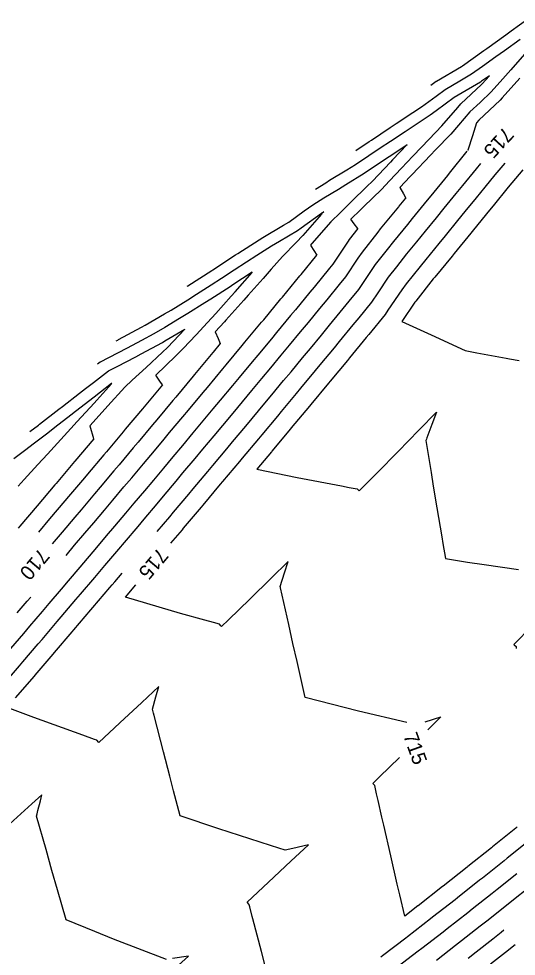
# Model space of a CAD drawing. Extents: x 1487507 to 1489130, y 497211 to 499439.
# Drawn here: x 1488402.4 to 1488484.6, y 498736.1 to 498891 of the extents above; entities that cross this region are included whole.
import ezdxf

# ---------------------------------------------------------------- set-up
doc = ezdxf.new("R2010")
doc.units = 0
for name, color, linetype in [('Prop CMT Ditch DDE', 7, 'Continuous'), ('Prop Drainage Ditch Flow Line', 7, 'Continuous'), ('Prop Drainage Structure Pipe Outlet Channel Detail CELL', 7, 'Continuous')]:
    doc.layers.add(name, color=color, linetype=linetype)

msp = doc.modelspace()

# ---------------------------------------------------------------- linework, layer by layer
at = {"layer": 'Prop CMT Ditch DDE'}
for points in [[(1488470.48, 498879.98), (1488471.36, 498880.63), (1488471.38, 498880.64), (1488475.53, 498883.09), (1488475.71, 498883.2), (1488479.21, 498885.69), (1488479.73, 498886.06), (1488482.84, 498888.3), (1488483.73, 498888.95), (1488486.49, 498890.96)], [(1488458.06, 498869.2), (1488460.25, 498870.67), (1488460.63, 498870.92), (1488463.74, 498872.99), (1488464.75, 498873.66), (1488467.51, 498875.47), (1488468.9, 498876.38), (1488471.35, 498878.18), (1488472.85, 498879.29), (1488475.26, 498880.7), (1488477.19, 498881.85), (1488479.02, 498883.15), (1488481.21, 498884.72), (1488482.62, 498885.73), (1488485.22, 498887.61)], [(1488485.96, 498885.11), (1488483.67, 498882.5), (1488482.35, 498881.02), (1488480.45, 498878.88), (1488478.6, 498877.14), (1488476.91, 498875.56), (1488475.05, 498873.4), (1488473.75, 498871.9), (1488471.23, 498869.28), (1488470.39, 498868.41), (1488467.35, 498865.2), (1488467.06, 498864.91), (1488465.32, 498863.06), (1488465.92, 498862.03), (1488466.33, 498861.33)], [(1488458.41, 498856.3), (1488457.81, 498857.08), (1488457.24, 498857.84), (1488458.83, 498859.38), (1488459.39, 498859.94), (1488462.29, 498862.76), (1488463.65, 498864.2), (1488465.6, 498866.27), (1488467.46, 498868.23), (1488468.93, 498869.77), (1488471.29, 498872.22), (1488472.28, 498873.25), (1488474.93, 498876.32), (1488475.44, 498876.91), (1488478.81, 498880.07), (1488478.97, 498880.23), (1488480.14, 498881.54), (1488480.13, 498881.55), (1488478.84, 498880.62), (1488478.67, 498880.5), (1488474.98, 498878.32), (1488474.32, 498877.93), (1488471.33, 498875.73), (1488470.37, 498875.02), (1488467.54, 498873.17), (1488466.21, 498872.3), (1488463.79, 498870.69), (1488462.09, 498869.56), (1488460.2, 498868.29), (1488457.99, 498866.81), (1488456.59, 498865.95), (1488453.74, 498864.21), (1488453.11, 498863.82), (1488451.39, 498862.76)], [(1488485.15, 498881.16), (1488482.24, 498877.88), (1488481.93, 498877.53), (1488478.39, 498874.22), (1488478.39, 498874.21), (1488478.01, 498873.78), (1488477.34, 498871.64), (1488476.6, 498869.27), (1488476.63, 498869.23)], [(1488430.18, 498846.77), (1488430.28, 498846.83), (1488430.29, 498846.84), (1488434.25, 498849.39), (1488434.42, 498849.5), (1488438.2, 498851.93), (1488438.55, 498852.16), (1488442.11, 498854.45), (1488442.69, 498854.83), (1488446.12, 498856.86), (1488446.98, 498857.37), (1488449.54, 498859.21), (1488450.95, 498860.23), (1488452.78, 498861.35), (1488455.19, 498862.83), (1488456.41, 498863.58), (1488459.44, 498865.44), (1488460.16, 498865.92), (1488463.55, 498868.19), (1488463.83, 498868.38), (1488466.55, 498870.19), (1488466.56, 498870.18), (1488464.14, 498867.64), (1488463.81, 498867.29), (1488460.83, 498864.13), (1488459.9, 498863.22), (1488457.37, 498860.76), (1488455.53, 498858.96), (1488453.92, 498857.39), (1488450.81, 498853.84), (1488450.74, 498853.76), (1488450.55, 498853.56), (1488450.61, 498853.45), (1488451.6, 498851.89)], [(1488425.24, 498806.23), (1488427.31, 498808.68), (1488427.95, 498809.44), (1488430.46, 498812.42), (1488431.17, 498813.27), (1488433.61, 498816.17), (1488434.44, 498817.16), (1488436.75, 498819.92), (1488437.71, 498821.06), (1488439.89, 498823.67), (1488440.94, 498824.94), (1488443.02, 498827.43), (1488444.16, 498828.81), (1488446.14, 498831.18), (1488447.36, 498832.65), (1488449.26, 498834.94), (1488450.56, 498836.5), (1488452.37, 498838.7), (1488453.74, 498840.36), (1488455.48, 498842.46), (1488456.98, 498844.29), (1488458.57, 498846.23), (1488460.1, 498848.52), (1488461.32, 498850.33), (1488463.29, 498852.84), (1488464.33, 498854.16), (1488466.64, 498856.98), (1488467.42, 498857.93), (1488469.93, 498861), (1488470.49, 498861.7), (1488473.25, 498865.08), (1488473.57, 498865.47), (1488476.49, 498869.07)], [(1488482.67, 498867.09), (1488481.04, 498865.17), (1488479.37, 498863.12), (1488477.96, 498861.38), (1488476.1, 498859.1), (1488474.88, 498857.6), (1488472.85, 498855.12), (1488471.78, 498853.81), (1488469.62, 498851.18), (1488468.69, 498850.03), (1488466.4, 498847.14), (1488465.66, 498846.18), (1488463.38, 498842.8), (1488462.89, 498842.07), (1488460.22, 498838.81), (1488459.79, 498838.28), (1488457.02, 498834.93), (1488456.67, 498834.51), (1488453.82, 498831.07), (1488453.55, 498830.74), (1488450.62, 498827.21), (1488450.41, 498826.96), (1488447.4, 498823.35), (1488447.27, 498823.2), (1488444.19, 498819.5), (1488444.13, 498819.43), (1488441.73, 498816.56), (1488448.37, 498815.18), (1488455.7, 498813.78), (1488456.98, 498813.54), (1488458.28, 498813.32), (1488458.34, 498813.26), (1488458.64, 498812.97), (1488461.58, 498815.93), (1488465.05, 498819.45), (1488468.5, 498822.98), (1488471.38, 498825.95), (1488470.62, 498823.92), (1488469.8, 498821.72), (1488469.72, 498821.5), (1488469.65, 498821.3), (1488470.51, 498815.99), (1488470.86, 498813.75), (1488471.48, 498810.16), (1488472.27, 498805.38), (1488472.47, 498804.28), (1488472.9, 498801.79), (1488476.51, 498801.19), (1488479.27, 498800.79), (1488484.93, 498799.94)], [(1488485.69, 498866.02), (1488483.25, 498863.13), (1488480.74, 498860.06), (1488480.16, 498859.34), (1488477.52, 498856.11), (1488477.07, 498855.55), (1488474.32, 498852.18), (1488473.97, 498851.76), (1488471.12, 498848.28), (1488470.86, 498847.97), (1488467.96, 498844.28), (1488467.83, 498844.11), (1488465.69, 498840.94), (1488470.49, 498838.73), (1488476.16, 498836.15), (1488478.09, 498835.78), (1488482.92, 498834.89), (1488483.44, 498834.79), (1488485.08, 498834.49)], [(1488399.82, 498780.97), (1488402.47, 498784.05), (1488403.02, 498784.69), (1488405.59, 498787.7), (1488406.21, 498788.42), (1488408.71, 498791.35), (1488409.39, 498792.15), (1488411.82, 498795.01), (1488412.57, 498795.89), (1488414.93, 498798.67), (1488415.74, 498799.62), (1488416.58, 498800.62), (1488418.91, 498803.35), (1488419.83, 498804.44), (1488422.07, 498807.09), (1488423.06, 498808.27), (1488425.22, 498810.83), (1488426.28, 498812.09), (1488428.36, 498814.57), (1488429.5, 498815.92), (1488431.51, 498818.31), (1488432.79, 498819.85), (1488434.64, 498822.05), (1488436.08, 498823.77), (1488437.77, 498825.8), (1488439.32, 498827.66), (1488440.89, 498829.54), (1488442.54, 498831.53), (1488444.01, 498833.29), (1488445.74, 498835.38), (1488447.12, 498837.04), (1488448.93, 498839.22), (1488450.23, 498840.79), (1488452.11, 498843.07), (1488453.33, 498844.54), (1488455.36, 498847.03), (1488456.4, 498848.31), (1488458.46, 498851.38), (1488459.15, 498852.4), (1488461.74, 498855.7), (1488462.16, 498856.23), (1488465.15, 498859.88), (1488465.23, 498859.98), (1488466.33, 498861.33)], [(1488458.41, 498856.3), (1488456.98, 498854.47), (1488456.82, 498854.23), (1488454.24, 498850.39), (1488453.73, 498849.77), (1488451.17, 498846.63), (1488450.47, 498845.79), (1488448.08, 498842.88), (1488447.29, 498841.94), (1488444.98, 498839.14), (1488444.11, 498838.1), (1488441.87, 498835.4), (1488440.92, 498834.26), (1488438.76, 498831.66), (1488437.7, 498830.39), (1488435.65, 498827.92), (1488434.45, 498826.49), (1488432.53, 498824.18), (1488431.14, 498822.53), (1488429.4, 498820.45), (1488427.83, 498818.57), (1488426.27, 498816.71), (1488424.61, 498814.75), (1488423.13, 498812.98), (1488421.4, 498810.93), (1488419.98, 498809.25), (1488418.17, 498807.11), (1488416.83, 498805.52), (1488414.94, 498803.29), (1488413.67, 498801.79), (1488412.46, 498800.36), (1488410.51, 498798.07), (1488409.35, 498796.7), (1488407.34, 498794.34), (1488406.23, 498793.05), (1488404.16, 498790.62), (1488403.12, 498789.39), (1488400.98, 498786.89)], [(1488410.17, 498802.28), (1488411.6, 498803.96), (1488413.29, 498805.96), (1488414.75, 498807.69), (1488416.52, 498809.78), (1488417.9, 498811.41), (1488419.74, 498813.6), (1488421.04, 498815.13), (1488422.95, 498817.41), (1488424.17, 498818.86), (1488426.15, 498821.23), (1488427.29, 498822.58), (1488429.49, 498825.21), (1488430.41, 498826.31), (1488432.82, 498829.2), (1488433.53, 498830.04), (1488436.08, 498833.11), (1488436.64, 498833.77), (1488439.3, 498836.98), (1488439.74, 498837.51), (1488442.49, 498840.82), (1488442.84, 498841.24), (1488445.66, 498844.66), (1488445.93, 498844.98), (1488448.84, 498848.5), (1488449.01, 498848.72), (1488451.6, 498851.89)], [(1488426.11, 498830.48), (1488425.67, 498831.09), (1488425, 498832.07), (1488428.33, 498835.25), (1488429.51, 498836.47), (1488431.66, 498838.72), (1488433.56, 498840.78), (1488434.93, 498842.26), (1488437.46, 498845.11), (1488438.12, 498845.86), (1488440.96, 498849.06), (1488440.95, 498849.06), (1488440.95, 498849.07), (1488437.76, 498847.01), (1488437.28, 498846.69), (1488434.08, 498844.63), (1488433.14, 498844.02), (1488430.3, 498842.26), (1488428.94, 498841.42), (1488426.48, 498839.96), (1488424.68, 498838.9), (1488422.63, 498837.79), (1488420.28, 498836.53), (1488418.68, 498835.7), (1488415.81, 498834.23), (1488415.36, 498833.88)], [(1488404.22, 498822.76), (1488405.61, 498823.82), (1488405.78, 498823.95), (1488408.98, 498826.43), (1488409.59, 498826.9), (1488412.4, 498829.08), (1488413.4, 498829.85), (1488414.7, 498830.86), (1488417.22, 498832.81), (1488418.61, 498833.52), (1488421.69, 498835.11), (1488422.59, 498835.59), (1488426.1, 498837.48), (1488426.5, 498837.72), (1488429.8, 498839.68), (1488429.81, 498839.67), (1488426.92, 498836.66), (1488426.12, 498835.9), (1488423.44, 498833.34), (1488421.13, 498831.23), (1488419.89, 498830.1), (1488417.09, 498827.01), (1488416.66, 498826.53), (1488414.1, 498823.72), (1488414.74, 498821.61), (1488414.75, 498821.58)], [(1488402.27, 498813.76), (1488403.26, 498814.84), (1488405.53, 498817.3), (1488407.13, 498819.04), (1488408.79, 498820.84), (1488410.98, 498823.25), (1488412.03, 498824.4), (1488414.8, 498827.45), (1488415.26, 498827.96), (1488417.72, 498830.67), (1488417.72, 498830.68), (1488417.71, 498830.68), (1488414.8, 498828.43), (1488411.75, 498826.06), (1488410.99, 498825.47), (1488408.35, 498823.42), (1488407.17, 498822.51), (1488404.95, 498820.82), (1488403.33, 498819.59), (1488401.55, 498818.23)], [(1488426.11, 498830.48), (1488423.08, 498826.86), (1488422.81, 498826.53), (1488419.97, 498823.15), (1488419.62, 498822.73), (1488416.85, 498819.43), (1488416.42, 498818.92), (1488413.73, 498815.72), (1488413.22, 498815.12), (1488410.6, 498812.02), (1488410, 498811.31), (1488407.46, 498808.31), (1488405.62, 498806.14)], [(1488414.76, 498821.58), (1488411.64, 498817.88), (1488411.56, 498817.79), (1488408.52, 498814.18), (1488408.35, 498813.98), (1488405.39, 498810.48), (1488402.56, 498807.14), (1488402.26, 498806.78)], [(1488401.85, 498778.76), (1488404.94, 498782.36), (1488405.06, 498782.49), (1488408.06, 498786), (1488408.26, 498786.23), (1488411.18, 498789.65), (1488411.45, 498789.97), (1488414.29, 498793.31), (1488414.63, 498793.71), (1488417.41, 498796.97), (1488417.81, 498797.45), (1488418.23, 498797.94), (1488419.43, 498799.36)], [(1488402.11, 498792.81), (1488403.76, 498794.74), (1488404.34, 498795.42)], [(1488487.2, 498790.63), (1488484.18, 498787.59), (1488484.24, 498787.54), (1488484.54, 498787.24), (1488484.59, 498786.93)], [(1488443.23, 498733.82), (1488442.46, 498736.87), (1488441.05, 498742.25), (1488440.95, 498742.62), (1488440.53, 498744.23), (1488440.45, 498744.55), (1488440.43, 498744.63), (1488440.1, 498744.98), (1488440.09, 498744.99), (1488443.65, 498748.31), (1488447.34, 498751.76), (1488450.22, 498754.47), (1488447.63, 498753.88), (1488446.37, 498753.6), (1488445.32, 498753.92), (1488443.94, 498754.37), (1488435.42, 498757.13), (1488429.03, 498759.29), (1488427.96, 498763.42), (1488427.32, 498765.8), (1488426.29, 498769.84), (1488424.72, 498775.84), (1488424.62, 498776.23), (1488424.45, 498776.91), (1488425.01, 498778.9), (1488425.5, 498780.64), (1488422.69, 498778), (1488419.09, 498774.62), (1488415.61, 498771.39), (1488415.28, 498771.74), (1488415.27, 498771.76), (1488414.88, 498771.89), (1488412.97, 498772.58), (1488404.84, 498775.52), (1488400.47, 498777.15)], [(1488426.8, 498735.52), (1488418.04, 498738.91), (1488414.95, 498740.14), (1488410.18, 498742.08), (1488408.78, 498747.03), (1488407.85, 498750.21), (1488406.88, 498753.7), (1488405.3, 498759.22), (1488405.39, 498759.57), (1488405.53, 498760.17), (1488405.93, 498761.75), (1488406.17, 498762.71), (1488404.55, 498761.24), (1488400.89, 498757.93)], [(1488486.59, 498755.08), (1488483.1, 498752.27), (1488482.57, 498751.83), (1488479, 498748.99), (1488478.53, 498748.61), (1488474.89, 498745.73), (1488474.48, 498745.4), (1488470.76, 498742.5), (1488470.41, 498742.23), (1488466.62, 498739.3), (1488466.32, 498739.07), (1488462.46, 498736.12), (1488462.22, 498735.93)], [(1488484.66, 498749.68), (1488481.42, 498747.09), (1488480.62, 498746.45), (1488477.29, 498743.82), (1488476.56, 498743.24), (1488473.16, 498740.58), (1488472.48, 498740.05), (1488469, 498737.37), (1488468.39, 498736.89), (1488464.83, 498734.18)], [(1488471.39, 498735.44), (1488474.55, 498737.88), (1488475.55, 498738.66), (1488478.63, 498741.07), (1488479.69, 498741.91), (1488482.7, 498744.29), (1488483.83, 498745.2), (1488486.75, 498747.53)], [(1488482.55, 498740.37), (1488482.09, 498740.01), (1488480.71, 498738.91), (1488477.94, 498736.75), (1488476.62, 498735.71)], [(1488428.76, 498734.59), (1488430.41, 498736.1), (1488427.78, 498735.67)]]:
    msp.add_lwpolyline(points, dxfattribs=at)
at = {"layer": 'Prop Drainage Ditch Flow Line'}
for points in [[(1488427.52, 498804.3), (1488429.4, 498806.53), (1488429.61, 498806.78), (1488432.56, 498810.28), (1488432.84, 498810.61), (1488435.72, 498814.04), (1488436.09, 498814.48), (1488438.87, 498817.79), (1488439.33, 498818.35), (1488442.01, 498821.55), (1488442.57, 498822.22), (1488445.15, 498825.31), (1488445.78, 498826.08), (1488448.28, 498829.07), (1488448.99, 498829.93), (1488451.4, 498832.84), (1488452.19, 498833.79), (1488454.52, 498836.6), (1488455.38, 498837.64), (1488457.64, 498840.37), (1488458.6, 498841.55), (1488460.73, 498844.15), (1488461.74, 498845.66), (1488463.49, 498848.26), (1488464.85, 498849.99), (1488466.51, 498852.1), (1488468.13, 498854.08), (1488469.6, 498855.87), (1488471.39, 498858.06), (1488472.68, 498859.65), (1488474.67, 498862.09), (1488475.76, 498863.42), (1488478, 498866.18), (1488478.71, 498867.04)], [(1488418.48, 498837.75), (1488418.74, 498837.88), (1488418.87, 498837.95), (1488422.67, 498839.99), (1488423.27, 498840.31), (1488426.47, 498842.21), (1488427.53, 498842.83), (1488430.29, 498844.54), (1488431.72, 498845.43), (1488434.17, 498847.01), (1488435.85, 498848.1), (1488437.98, 498849.47), (1488439.99, 498850.77), (1488441.73, 498851.89), (1488444.13, 498853.44), (1488445.46, 498854.23), (1488448.42, 498855.98), (1488449.01, 498856.41), (1488452.39, 498858.85), (1488452.44, 498858.87), (1488452.78, 498859.08), (1488452.78, 498859.08), (1488452.79, 498859.08), (1488452.47, 498858.77), (1488452.4, 498858.68), (1488449.3, 498855.14), (1488448.2, 498854.01), (1488445.95, 498851.68), (1488444.08, 498849.57), (1488442.75, 498848.07), (1488440.28, 498845.28), (1488439.55, 498844.46), (1488436.61, 498841.15), (1488436.35, 498840.86), (1488434.83, 498839.21), (1488435.3, 498838.15), (1488435.67, 498837.29)], [(1488435.67, 498837.29), (1488434.51, 498835.89), (1488434.46, 498835.83), (1488431.41, 498832.16), (1488431.19, 498831.91), (1488428.3, 498828.44), (1488427.84, 498827.9), (1488425.19, 498824.72), (1488424.48, 498823.88), (1488422.07, 498821), (1488421.28, 498820.07), (1488418.94, 498817.28), (1488418.08, 498816.26), (1488415.81, 498813.57), (1488414.87, 498812.45), (1488412.68, 498809.85), (1488411.64, 498808.63), (1488409.53, 498806.14), (1488407.9, 498804.21)], [(1488466.48, 498774.66), (1488458.53, 498776.56), (1488449.67, 498778.84), (1488448.35, 498784.75), (1488447.66, 498787.75), (1488446.97, 498790.9), (1488445.62, 498796.93), (1488445.61, 498797.01), (1488445.57, 498797.17), (1488446.3, 498799.43), (1488446.88, 498801.26), (1488444.08, 498798.51), (1488440.54, 498795.06), (1488437, 498791.63), (1488435.88, 498790.55), (1488435.77, 498790.67), (1488435.54, 498790.92), (1488434.52, 498791.2), (1488433.12, 498791.59), (1488429.11, 498792.71), (1488419.99, 498795.41), (1488421.71, 498797.43)], [(1488469.52, 498774.79), (1488472.13, 498775.6), (1488469.98, 498773.49)], [(1488484.75, 498757.44), (1488484.49, 498757.23), (1488480.68, 498754.15), (1488480.48, 498753.98), (1488476.59, 498750.88), (1488476.45, 498750.77), (1488472.49, 498747.64), (1488472.4, 498747.57), (1488468.37, 498744.42), (1488468.34, 498744.4), (1488466.15, 498742.7), (1488465.34, 498746.2), (1488464.91, 498748), (1488463.86, 498752.66), (1488462.68, 498757.71), (1488462.38, 498759.07), (1488461.77, 498761.8), (1488461.51, 498762.92), (1488461.21, 498764.27), (1488461.1, 498764.38), (1488460.86, 498764.63), (1488462, 498765.73), (1488465.26, 498768.88)], [(1488480.33, 498734.83), (1488482.79, 498736.74), (1488484.41, 498738.03)]]:
    msp.add_lwpolyline(points, dxfattribs=at)

# ---------------------------------------------------------------- texts
at = {"layer": 'Prop Drainage Structure Pipe Outlet Channel Detail CELL'}
for s, rotation, p in [('715', 227.6004, (1488482.6, 498873.25)), ('710', 229.6709, (1488405.81, 498803.61)), ('715', 229.7969, (1488425.45, 498803.71)), ('715', 289.7699, (1488465.86, 498772.53))]:
    msp.add_text(s, height=2.4, rotation=rotation, dxfattribs=at).set_placement(p)

doc.saveas('drawing.dxf')
